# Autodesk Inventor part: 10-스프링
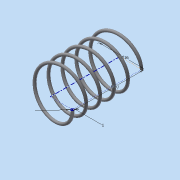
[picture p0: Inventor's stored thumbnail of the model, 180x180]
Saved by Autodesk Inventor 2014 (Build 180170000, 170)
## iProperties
Created: 2015-06
Part Number: 10-스프링
Material: 강철, 연강
Document SubType Name: Modeling
Designer: MYHOME
Density: 1 g/cm^3
Appearance: 강철
Author: MYHOME
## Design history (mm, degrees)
sketch "스케치1"
  geometry: L1 (0, 0)-(8, 0); L2 (8, 0)-(8, 14.5); L3 (8, 14.5)-(0, 14.5); L4 (0, 14.5)-(0, 0); C1 r 0.5 at (8, 0)
  constraints: 8 end point, 2 parallel, 1 centre point, 1 coincident, 1 horizontal, 1 perpendicular
  dimensions: "d0" = 1 diameter of C1; "d1" = 16 diameter of L2 L4; "d2" = 14.5 distance of L1.end L2.end (derived)
feature "코일1" sketch "스케치1" pitch "d3" = 10; turns "d5" = 5; dims "d4" = 14.5 (= d2), "d6" = 0, angle "d7" = 90 deg, angle "d8" = 90 deg, "d9" = 0, "d10" = 0
sketch "스케치2"
  geometry: L1 (-8.5, 0)-(-7.5, 0) reference; 1 further point
  constraints: 1 horizontal alignment
extrude "돌출1" cut sketch "스케치2" stored distance "d11" = 10; taper "d12" = 0 deg
node "작업 평면1"
sketch "스케치3"
  geometry: L1 (-7.5, 0)-(-8.5, 0) reference; 1 further point
  constraints: 1 horizontal alignment
extrude "돌출2" cut sketch "스케치3" stored distance "d14" = 10; taper "d15" = 0 deg
node "솔리드1"
node "절단 모서리 투영1"
node "절단 모서리 투영2"
other parameters: "d13" = 14.5 (= d2)
